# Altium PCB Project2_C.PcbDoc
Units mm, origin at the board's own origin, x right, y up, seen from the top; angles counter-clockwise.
Board outline 100 x 50 mm, 2 copper layers (Top Layer, Bottom Layer); 57 components, 59 nets, 255 pads, 69 vias.
Unrouted connection lines stored in the file: 2.
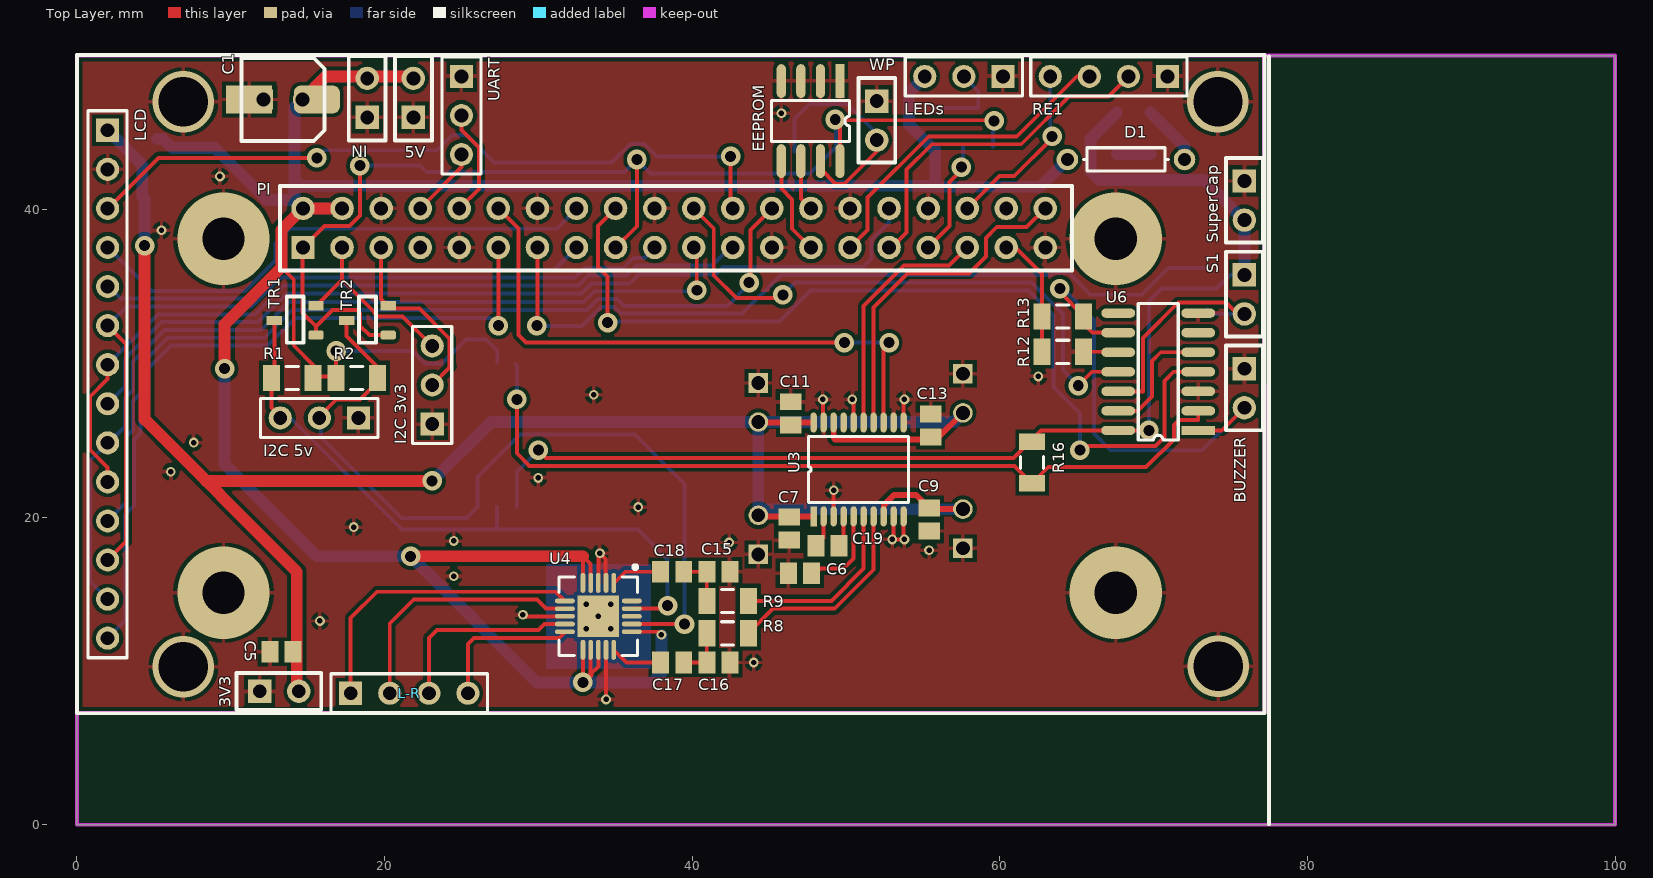
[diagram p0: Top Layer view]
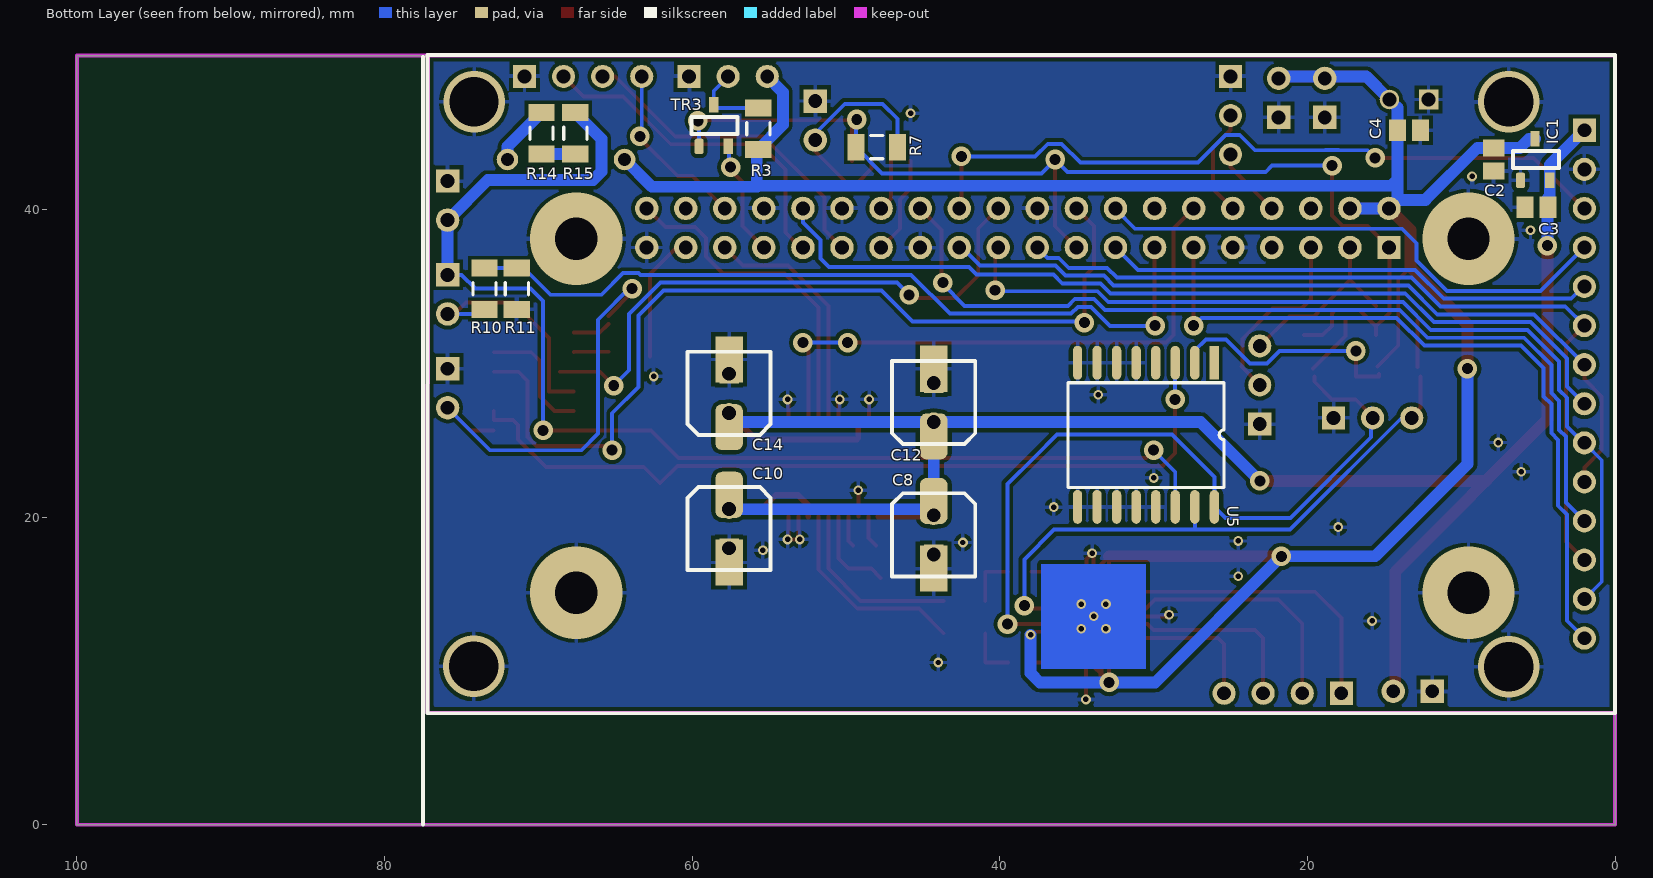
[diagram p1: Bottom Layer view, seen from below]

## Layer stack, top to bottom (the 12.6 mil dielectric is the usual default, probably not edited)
Top Solder: solder mask 0.0102, Solder Resist, Dk 3.5
Top Layer: signal copper 0.0356
Dielectric 1: dielectric 0.32, FR-4, Dk 4.8
Bottom Layer: signal copper 0.0356
Bottom Solder: solder mask 0.0102, Solder Resist, Dk 3.5

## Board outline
0,0 100,0 100,50 0,50

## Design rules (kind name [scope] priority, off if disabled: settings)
Clearance [All] p1: gap=0.254
PolygonConnect [All] p1: connectstyle=Relief reliefconductorwidth=0.254 reliefentries=4 polygonreliefangle="90 Angle" airgapwidth=0.254
RoutingVias [All] p1: holewidth=0.711 width=1.27 viastyle="Through Hole" minholewidth=0.711 minwidth=1.27 maxholewidth=0.711 maxwidth=1.27
SolderMaskExpansion [All] p1: expansion=0.102
Width [All] p1: maxlimit=1.524 minlimit=0.254 preferedwidth=0.254
30 further rules are at their usual default settings.

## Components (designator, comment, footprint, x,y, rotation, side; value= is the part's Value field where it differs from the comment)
3V3 "" HDR1X2 11.887,8.677 r0 top
5V "" HDR1X2 21.873,45.983 r90 top
BUZZER "" HDR1X2 75.9,29.65 r270 top
C1 "" "SMD CAP 6X5" 13.4,47.15 r180 top
C2 "" C0805 7.9,43.248 r90 bottom
C3 "" C0805 5.1,40.15 r180 bottom
C4 "" C0805 13.4,45.15 r0 bottom
C5 "" C0805 13.3,11.25 r180 top
C6 "" C0805 47,16.35 r0 top
C7 "" C0805 46.3,19.25 r270 top
C8 "" "SMD CAP 6X5" 44.3,18.85 r270 bottom
C9 "" C0805 55.4,19.85 r270 top
C10 "" "SMD CAP 6X5" 57.6,19.25 r270 bottom
C11 "" C0805 46.4,26.75 r270 top
C12 "" "SMD CAP 6X5" 44.3,27.45 r90 bottom
C13 "" C0805 55.5,25.95 r90 top
C14 "" "SMD CAP 6X5" 57.6,28.05 r90 bottom
C15 "" C0805 41.7,16.45 r0 top
C16 "" C0805 41.7,10.55 r0 top
C17 "" C0805 38.7,10.55 r0 top
C18 "" C0805 38.7,16.45 r0 top
C19 "" C0805 48.8,18.15 r0 top
D1 "" AXIAL-0.3 68.2,43.25 r0 top
EEPROM "I²C SERIAL EEPROM" SOIC-8 47.7,45.75 r270 top
"I2C 3v3" "" HDR1X3 23.1,26.05 r90 top
"I2C 5v" "" HDR1X3 18.3,26.45 r180 top
IC1 "3v3" SOT-23A 5.2,43.248 r180 bottom
IN "" HDR1X2 18.873,45.983 r90 top
L-R "Header 4" HDR1X4 17.8,8.55 r0 top
LCD "TJCTM24024-SPI" HDR1X14 2,45.15 r270 top locked
LEDs "WS2812" HDR1X3 60.2,48.65 r180 top
PI "Raspberry Pi v2" HDR2X10 38.83,38.8 r90 top locked
R1 "" C1206 14,29.05 r0 top
R2 "" C1206 18.2,29.05 r180 top
R3 "" C1206 55.7,45.25 r90 bottom
R7 "" C1206 48,44.05 r0 bottom
R8 "" C1206 42.3,12.45 r180 top
R9 "" C1206 42.3,14.55 r180 top
R10 "" C1206 73.5,34.85 r270 bottom
R11 "" C1206 71.4,34.85 r90 bottom
R12 "" C1206 64.1,30.75 r180 top
R13 "" C1206 64.1,33.05 r180 top
R14 "" C1206 69.8,44.95 r270 bottom
R15 "" C1206 67.6,44.95 r90 bottom
R16 "" C1206 62.1,23.55 r90 top
RE1 "RotaryEncoder" HDR1X4 70.9,48.65 r180 top
S1 "Alarm reset" HDR1X2 75.9,35.75 r270 top
SuperCap "Supercap" HDR1X2 75.9,41.85 r270 top
TR1 "Level shifter" SOT-23A 14.192,32.785 r90 top
TR2 "Level shifter" SOT-23A 18.885,32.785 r90 top
TR3 "Level shifter" SOT-23A 58.6,45.45 r180 bottom
U3 "I²S DAC" TSSOP-20 47.9,20.05 r90 top
U4 "TPA2016D2" QFN20-TPA2016D2 33.9,13.55 r270 top
U5 "DS3231 RTC" "DS3231 SO-16" 30.5,25.35 r270 bottom
U6 "NOR gates" SOIC-14 70.3,29.45 r180 top
UART "" HDR1X3 25,48.65 r270 top
WP "Jumper" HDR1X2 52,47.05 r270 top

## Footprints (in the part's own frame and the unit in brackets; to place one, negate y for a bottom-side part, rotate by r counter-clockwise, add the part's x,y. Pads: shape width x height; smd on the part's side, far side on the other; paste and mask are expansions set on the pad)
AXIAL-0.3 [mm] "Axial Device, Thru-Hole; 2 Leads; 0.3 in Pin Spacing"
  round 1.4 hole 0.85: 1(-3.81,0) 2(3.81,0)
  silkscreen extent -2.77,-0.76 2.77,0.76
C0805 [mm] "Chip Capacitor, Body 2.0x1.3mm, IPC High Density"
  rect 1.1x1.4 smd: 1(-0.75,0) 2(0.75,0)
  body extent -1.1,-0.72 1.1,0.72, height 1.4
C1206 [mm] "Chip Capacitor, Body 3.2x1.6mm, IPC High Density"
  rect 1.1x1.7 smd: 1(-1.35,0) 2(1.35,0)
  silkscreen extent -0.4,-0.75 0.4,0.75, body extent -1.7,-0.9 1.7,0.9, height 1.3
"DS3231 SO-16" [mm]
  rect 2.2x0.6 smd: 1(-4.685,4.445)
  oval 2.2x0.6 smd: 2(-4.685,3.175) 3(-4.685,1.905) 4(-4.685,0.635) 5(-4.685,-0.635) 6(-4.685,-1.905) 7(-4.685,-3.175) 8(-4.685,-4.445) 9(4.685,-4.445) 10(4.685,-3.175) 11(4.685,-1.905) 12(4.685,-0.635) 13(4.685,0.635) 14(4.685,1.905) 15(4.685,3.175) 16(4.685,4.445)
  silkscreen extent -3.38,-5.08 3.41,5.08
HDR1X2 [mil] "2 Pin Header"
  rect 60x60 hole 35.43: 1(0,0)
  round 60 hole 35.43: 2(100,0)
  silkscreen extent -59,-47 157,47
HDR1X3 [mm] "Connector; Header; 3 Position"
  rect 1.5x1.5 hole 0.9: 1(0,0)
  round 1.5 hole 0.9: 2(2.54,0) 3(5.08,0)
  silkscreen extent -1.27,-1.27 6.35,1.27
HDR1X4 [mm] "Connector; Header; 4 Position"
  rect 1.5x1.5 hole 0.9: 1(0,0)
  round 1.5 hole 0.9: 2(2.54,0) 3(5.08,0) 4(7.62,0)
  silkscreen extent -1.27,-1.27 8.89,1.27
HDR1X14 [mm] "Connector; Header; 14 Position"
  rect 1.5x1.5 hole 0.9: 1(0,0)
  round 1.5 hole 0.9: 2(2.54,0) 3(5.08,0) 4(7.62,0) 5(10.16,0) 6(12.7,0) 7(15.24,0) 8(17.78,0) 9(20.32,0) 10(22.86,0) 11(25.4,0) 12(27.94,0) 13(30.48,0) 14(33.02,0)
  silkscreen extent -1.27,-1.27 34.29,1.27
HDR2X10 [mil] "20 pin Header"
  rect 60x60 hole 35.43: 1(-50,950)
  round 60 hole 35.43: 2(50,950) 3(-50,850) 4(50,850) 5(-50,750) 6(50,750) 7(-50,650) 8(50,650) 9(-50,550) 10(50,550) 11(-50,450) 12(50,450) 13(-50,350) 14(50,350) 15(-50,250) 16(50,250) 17(-50,150) 18(50,150) 19(-50,50) 20(50,50) 21(-50,-50) 22(50,-50) 23(-50,-150) 24(50,-150) 25(-50,-250) 26(50,-250) 27(-50,-350) 28(50,-350) 29(-50,-450) 30(50,-450) 31(-50,-550) 32(50,-550) 33(-50,-650) 34(50,-650) 35(-50,-750) 36(50,-750) 37(-50,-850) 38(50,-850) 39(-50,-950) 40(50,-950)
  silkscreen extent -109,-1019 107,1009
QFN20-TPA2016D2 [mm] "QFN, 20-Leads, Body 4,77x4,77mm, Pitch 0,50mm, Thermal Pad 2,70x2,70mm, IPC Low Density"
  rect 2.7x2.7 smd: 0(0,0)
  oct 1.3x0.3 smd: 1(-2.175,1)
  oval 1.3x0.3 smd: 2(-2.175,0.5) 3(-2.175,0) 4(-2.175,-0.5) 5(-2.175,-1) 11(2.175,-1) 12(2.175,-0.5) 13(2.175,0) 14(2.175,0.5) 15(2.175,1)
  oval 0.3x1.3 smd: 6(-1,-2.175) 7(-0.5,-2.175) 8(0,-2.175) 9(0.5,-2.175) 10(1,-2.175) 16(1,2.175) 17(0.5,2.175) 18(0,2.175) 19(-0.5,2.175) 20(-1,2.175)
  silkscreen extent -3.32,-2.55 2.55,2.55, body extent -2.4,-2.4 2.4,2.4, height 0.8
"SMD CAP 6X5" [mm]
  rrect50% 3x1.8 smd: 1(-2.2,0)
  round 1.27 hole 0.9: 1(-1.27,0)
  rect 1.27x1.27 hole 0.9: 2(1.27,0)
  rect 3x1.8 smd: 2(2.2,0)
  silkscreen extent -2.7,-2.7 2.7,2.7
SOIC-8 [mm]
  rect 2.2x0.6 smd: 1(-2.6,1.905)
  oval 2.2x0.6 smd: 2(-2.6,0.635) 3(-2.6,-0.635) 4(-2.6,-1.905) 5(2.6,-1.905) 6(2.6,-0.635) 7(2.6,0.635) 8(2.6,1.905)
  silkscreen extent -1.33,-2.54 1.34,2.54
SOIC-14 [mm]
  rect 2.2x0.6 smd: 1(-2.6,3.81)
  oval 2.2x0.6 smd: 2(-2.6,2.54) 3(-2.6,1.27) 4(-2.6,0) 5(-2.6,-1.27) 6(-2.6,-2.54) 7(-2.6,-3.81) 8(2.6,-3.81) 9(2.6,-2.54) 10(2.6,-1.27) 11(2.6,0) 12(2.6,1.27) 13(2.6,2.54) 14(2.6,3.81)
  silkscreen extent -1.3,-4.44 1.3,4.44
SOT-23A [mm]
  rrect50% 0.6x1 smd: 1(-0.95,-1.35)
  rect 0.6x1 smd: 2(0.95,-1.35) 3(0,1.35)
  silkscreen extent -1.45,-0.55 1.55,0.55
TSSOP-20 [mm]
  rect 1.3x0.4 smd: 1(0,0)
  oval 1.3x0.4 smd: 2(0,-0.65) 3(0,-1.3) 4(0,-1.95) 5(0,-2.6) 6(0,-3.25) 7(0,-3.9) 8(0,-4.55) 9(0,-5.2) 10(0,-5.85) 11(6.1,-5.85) 12(6.1,-5.2) 13(6.1,-4.55) 14(6.1,-3.9) 15(6.1,-3.25) 16(6.1,-2.6) 17(6.1,-1.95) 18(6.1,-1.3) 19(6.1,-0.65) 20(6.1,0)
  silkscreen extent 0.9,-6.18 5.2,0.33

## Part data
3V3 5V IN: library part "Header 2", "Header, 2-Pin"
BUZZER: library part Bell, "Electrical Bell"
C1 SuperCap: library part "Cap Pol1", "Polarized Capacitor (Radial)"
C2 C3 C4 C5 C6 C7 C9 C11 C13 C15 C16 C17 C18 C19: library part Cap, "Capacitor"
C8 C10 C12 C14: library part "Cap Pol2", "Polarized Capacitor (Axial)"
D1: library part Diode, "Default Diode"
"I2C 3v3" "I2C 5v" LEDs UART: library part "Header 3", "Header, 3-Pin"
IC1: library part MCP1703, "Power regulator"
L-R: "Header, 4-Pin"
LCD: "LCD module"
PI: library part RaspberryPiV2, "Raspberry Pi v2 Header"
R1 R2 R3 R7 R8 R9 R10 R11 R12 R13 R14 R15 R16: library part Res2, "Resistor"
RE1: library part "Header 4", "Header, 4-Pin"
S1: library part SW-PB, "Switch"
TR1 TR2 TR3: library part AN10441, "Level Shifter"
U3: library part PCM5102A
U4: "I²C Audio Amplifier"
U5: library part DS3231, "RTC"
U6: library part 744002, "Dual 4-input NOR gate"

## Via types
v1: diameter 1.27, hole 0.711, Top Layer to Bottom Layer, tented both sides, 30 vias
v2: diameter 0.635, hole 0.356, Top Layer to Bottom Layer, tented both sides, 26 vias
v3: diameter 0.635, hole 0.356, Top Layer to Bottom Layer, 5 vias
v4: diameter 4, hole 3.2, Top Layer to Bottom Layer, 4 vias
v5: diameter 6, hole 2.75, Top Layer to Bottom Layer, 4 vias

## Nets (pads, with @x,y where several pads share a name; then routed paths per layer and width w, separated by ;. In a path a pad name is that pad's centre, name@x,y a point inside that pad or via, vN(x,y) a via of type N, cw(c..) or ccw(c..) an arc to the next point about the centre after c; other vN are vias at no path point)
3V3: 3V3.2 C3.2 C5.1 C7.1 C8.1 C9.1 C10.1 C11.2 C12.1 C13.1 C14.1 IC1.2 LCD.1 U3.1 U3.8 U3.17 U3.18 U3.20 | length 136.1
  Top Layer w0.381: C8.1@44.3,20.12 44.37,20.05 U3.1 ; C12.1@44.3,26.18 44.33,26.15 U3.20 ; U3.18 49.206,26.15 49.206,25.142 49.292,25.055 55.875,25.055 C14.1@57.6,26.78 ; U3.8 52.456,20.055 52.456,20.767 53.139,21.45 54.55,21.45 C9.1 55.48,20.52 C10.1@57.6,20.52
  Top Layer w0.762: v1(4.4,37.65) 4.4,26.35 14.3,16.45 3V3.2@14.3,8.55 ; 8.4,22.35 v1(23.1,22.35)
  Bottom Layer w0.762: LCD.1@1.965,45.15 LCD.1 4.25,42.9 C3.2@4.25,40.85 ; C3.2@4.35,40.75 4.4,40.7 v1(4.4,37.65) ; v1(23.1,22.35) 26.93,26.18 C12.1@44.3,26.18 ; C10.1@57.6,20.52 44.7,20.52 44.3,20.12 44.3,21.05 44.3,25.25 C12.1@44.3,26.18 ; C14.1@57.6,26.78 57,26.18 C12.1@44.3,26.18
3V3PI: EEPROM.8 PI.1 PI.17 R7.2 TR1.1 TR2.1 TR3.1 | length 76.2
  Top Layer w0.254: v1(18.4,42.85) 18.4,39.614 17.713,38.927 16.097,38.927 PI.1 14.661,37.491 14.661,33.277 14.884,33.054 14.896,33.054 15.542,32.408 ; TR2.1 19.015,31.835 18.416,32.434 18.416,33.243 18.193,33.466 16.616,33.466 15.55,32.4 15.542,32.408 ; PI.17 36.4,38.91 v1(36.4,43.25) ; EEPROM.8 49.605,45.345 49.3,45.65 v1(49.3,45.85) 49.35,45.8 v1@59.4,45.8 ; v1@59.434,45.766 v1(59.623,45.766) ; 15.542,32.408 TR1.1 15.542,32.408
  Bottom Layer w0.254: v1(18.4,42.85) 22.3,42.85 22.711,42.439 35.589,42.439 v1(36.4,43.25) 37.3,42.35 47.65,42.35 R7.2 49.35,45.8 v1(49.3,45.85) ; TR3.1 59.55,45.693 v1(59.623,45.766)
5V: 5V.2 C1.1 C2.2 C4.2 D1.1 IC1.3 IN.2 LEDs.3 PI.2 PI.4 R1.2 R2.2 R3.1 U4.4 U4.5 U4.11 U4.12 U4.13 U4.16 U5.2 | length 200
  Top Layer w0.254: 13.303,36.247 14.1,35.45 14.1,31.15 R1.2@15.45,29.8 ; R1.2@15.35,29.3 15.35,29.15 16.85,29.15 v1(16.85,30.8) ; v1@32.9,9.65 U4.11 ; U4.5 32.9,17.45 33.4,16.95 U4.4 ; 33.4,9.75 33.4,9.8 ; U4.12 33.4,9.8 ; U4.13 33.9,10.3 33.4,9.8 ; U4.16 37.8,12.55 v2(38,12.35)
  Top Layer w0.381: v1(32.9,9.25) 33.4,9.75
  Top Layer w0.762: v1(9.6,29.65) 9.6,32.544 13.303,36.247 13.303,38.673 PI.2 PI.4 ; C1.1@14.67,47.15 16.17,48.65 5V.2@22,48.65 ; v1(21.7,17.45) 32.9,17.45
  Bottom Layer w0.254: v1(16.85,30.8) 21.831,30.8 22.632,29.999 23.749,29.999 25.3,31.55 26.6,31.55 27.325,30.825 U5.2
  Bottom Layer w0.762: IC1.3 5.595,44.598 6.195,43.998 C2.2 8.952,43.998 12.33,40.62 14.15,40.62 ; v1(9.6,29.65) 9.6,23.45 15.6,17.45 v1(21.7,17.45) 29.9,9.25 v1(32.9,9.25) 37.4,9.25 38,9.85 v2(38,12.35) ; PI.4 PI.2 14.15,40.62 ; 5V.2@22,48.65 16.17,48.65 14.67,47.15 14.15,46.63 C4.2 14.15,41.95 ; LEDs.3 54.1,47.63 54.1,45.5 R3.1 ; 55.8,41.65 R3.1@55.8,43.9 ; D1.1 62.62,41.48 55.77,41.48 55.7,41.55 14.55,41.55 14.15,41.95 ; 14.15,40.62 14.15,41.95
5VBCK: R15.2 R16.2 S1.1 SuperCap.2 U5.14 U6.14 | length 79.6
  Top Layer w0.254: v1(30,24.35) 30.5,23.85 60.9,23.85 62.69,25.64 U6.14 v1(69.69,25.64)
  Bottom Layer w0.254: U5.14 28.595,22.945 v1(30,24.35) ; v1(69.69,25.64) 69.69,34.04 70.5,34.85 74.089,34.85 74.989,35.75 S1.1
  Bottom Layer w0.762: R15.2 65.9,44.6 65.9,42.45 66.435,41.915 73.295,41.915 SuperCap.2 S1.1
BUZZ: PI.37 R12.2 R13.2 | length 8.4
  Top Layer w0.254: PI.37 61.02,37.53 62.75,35.8 R12.2@62.75,30.45
"CE 0": LCD.3 PI.24 | length 47.7
  Top Layer w0.254: LCD.3 2.02,40.07 5.3,43.35 v1(15.6,43.35) ; v1@42.5,43.67 42.5,40.21 PI.24
  Bottom Layer w0.254: v1(15.6,43.35) 16.1,43.85 17.963,43.85 17.979,43.866 18.821,43.866 18.837,43.85 23.4,43.85 24.4,44.85 25.319,44.85 27.119,43.05 34.763,43.05 35.979,44.266 36.884,44.266 37.7,43.45 v1(42.5,43.45)
"CE 1": LCD.11 PI.26 | length 58.7
  Top Layer w0.254: v1(43.7,35.25) 43.783,35.333 43.783,38.673 PI.26
  Bottom Layer w0.254: LCD.11 3.2,20.95 3.2,25.232 3.639,25.671 3.639,27.552 4.147,28.06 4.147,29.897 5.911,31.661 12.193,31.661 13.998,33.466 33.161,33.466 33.869,34.174 35.131,34.174 35.571,33.734 42.284,33.734 43.7,35.15 v1(43.7,35.25)
CLK: PI.12 U3.13 | length 38.6
  Top Layer w0.254: PI.12 28.7,38.77 28.7,31.85 29.2,31.35 v1(49.9,31.35) ; U3.13 52.45,31.3 52.5,31.35 v1(52.8,31.35)
  Bottom Layer w0.254: v1(49.9,31.35) v1(52.8,31.35)
DC_LCD: LCD.5 PI.15 | length 32.2
  Bottom Layer w0.254: LCD.5 2.06,34.99 2.849,34.201 11.141,34.201 13.014,36.074 31.024,36.074 PI.15
DIN: PI.38
DOUT: PI.40 U3.14 | length 22
  Top Layer w0.254: U3.14 51.784,26.166 51.784,33.634 53.992,35.842 56.91,35.842 56.918,35.85 58,35.85 59.1,36.95 59.1,38.15 59.8,38.85 61.74,38.85 PI.40
FS: PI.35 U3.15 | length 15.9
  Top Layer w0.254: U3.15 51.15,33.718 53.782,36.35 56.7,36.35 PI.35
GND: 3V3.1 5V.1 "I2C 3v3.1" "I2C 5v.1" BUZZER.1 C1.2 C2.1 C3.1 C4.1 C5.2 C6.1 C7.2 C8.2 C9.2 C10.2 C11.1 C12.2 C13.2 C14.2 C15.2 C16.2 EEPROM.1 EEPROM.2 EEPROM.3 EEPROM.4 IC1.1 IN.1 LCD.2 LEDs.1 PI.6 PI.9 PI.14 PI.20 PI.25 PI.30 PI.34 PI.39 R11.1 R12.1 RE1.1 SuperCap.1 U3.3 U3.9 U3.10 U3.11 U3.12 U3.16 U3.19 U4.2 U4.3 U4.8 U4.14 U5.5 U5.6 U5.7 U5.8 U5.9 U5.10 U5.11 U5.12 U5.13 U6.3 U6.7 U6.10 UART.1 WP.1 | length 22.1
  Top Layer w0.254: v2(29,13.65) 29.1,13.55 U4.8 ; U4.3 33.9,17.55 v2(34,17.65) 34.369,17.281 U4.2@34.369,15.725 ; v2(34.4,8.15) U4.14 ; U3.19@48.5,26.2 v2(48.5,27.65) ; U3.3 v2(49.2,21.75) ; v2(50.4,27.65) 50.5,27.55 U3.16 ; v2(53,18.55) v2(53.8,18.55) ; v2@53.1,18.65 U3.9 ; v2@53.75,18.6 U3.10 ; U3.11 v2@53.75,27.6 ; R12.1 67.67,30.75 U6.10
  other v2: 44,10.55 15.8,13.25 24.5,16.15 55.4,17.85 42.4,18.35 24.5,18.45 18,19.35 36.5,20.65 30,22.55 6.1,22.95 7.6,24.85 53.8,27.65 33.6,27.95 62.5,29.15 5.5,38.65 9.3,42.15 45.8,46.25
  other v4: 6.92,10.27 74.2,10.3 6.92,47 74.18,47
  other v5: 9.53,15.09 67.53,15.09 9.53,38.09 67.53,38.09
IRQ: LCD.14 PI.11 | length 48
  Top Layer w0.254: v1(27.4,32.45) PI.11
  Bottom Layer w0.254: LCD.14 3.131,13.261 3.131,20.163 3.708,20.74 3.708,25.021 4.147,25.46 4.147,27.342 4.655,27.85 4.655,29.687 6.121,31.153 12.403,31.153 14.2,32.95 26.9,32.95 v1(27.4,32.45)
MISO: LCD.9 LCD.13 PI.21 | length 58.7
  Top Layer w0.254: PI.21 40.3,37.33 v1(40.3,34.75)
  Bottom Layer w0.254: LCD.13 0.869,15.801 0.869,23.699 LCD.9 2.115,24.945 2.195,24.945 3.131,25.881 3.131,27.763 3.639,28.271 3.639,30.107 5.701,32.169 11.983,32.169 13.788,33.974 32.95,33.974 33.658,34.682 40.368,34.682 v1(40.3,34.75)
MOSI: LCD.6 LCD.12 PI.19 | length 53.9
  Top Layer w0.254: LCD.12 3.2,18.41 3.2,31.25 LCD.6
  Bottom Layer w0.254: LCD.6 3.243,33.693 11.351,33.693 13.224,35.566 32.387,35.566 33.027,36.206 35.519,36.206 36.171,36.858 36.888,36.858 PI.19
NetBUZZER_2: BUZZER.2 R13.1 U6.1 U6.9 | length 30.6
  Top Layer w0.254: v1(63.9,34.85) 63.9,34.634 R13.1@65.45,33.084 ; R13.1@65.45,32.55 66.01,31.99 U6.9 ; U6.1 74.43,25.64 BUZZER.2
  Bottom Layer w0.254: v1(63.9,34.85) 63.9,35.05 66.116,32.834 66.116,25.434 67.2,24.35 73.14,24.35 BUZZER.2
NetC6_2: C6.2 U3.5 | length 6
  Top Layer w0.254: C6.2@47.75,16.05 48.35,16.65 49.839,16.65 50.5,17.311 U3.5
NetC15_1: C15.1 C18.2 R9.2 | length 3.4
  Top Layer w0.254: C18.2 C15.1 R9.2
NetC16_1: C16.1 C17.2 R8.2 | length 3.4
  Top Layer w0.254: C17.2 C16.1 R8.2
NetC17_1: C17.1 U4.15 | length 3.4
  Top Layer w0.254: U4.15 35.725,10.55 C17.1
NetC18_1: C18.1 U4.1 | length 3.3
  Top Layer w0.254: U4.1@34.931,15.725 35.656,16.45 C18.1
NetC19_1: C19.1 U3.2 | length 2.1
  Top Layer w0.254: C19.1 48.55,18.65 U3.2
NetC19_2: C19.2 U3.4 | length 2
  Top Layer w0.254: C19.2 49.85,18.45 U3.4
NetD1_2: D1.2 R14.1 | length 4
  Bottom Layer w0.762: R14.1 72.01,44.09 D1.2
NetEEPROM_5: EEPROM.5 PI.27 | length 6.4
  Top Layer w0.254: EEPROM.5 45.795,41.355 46.5,40.65 46.5,38.75 PI.27
NetEEPROM_6: EEPROM.6 PI.28 | length 3.4
  Top Layer w0.254: EEPROM.6 47.065,40.725 PI.28
NetEEPROM_7: EEPROM.7 R7.1 WP.2 | length 15.5
  Top Layer w0.254: EEPROM.7 48.335,42.657 49.323,41.669 49.887,41.669 52,43.782 WP.2 WP.2@51.879,44.631
  Bottom Layer w0.254: R7.1@46.65,43.75 46.65,45.9 47.616,46.866 50.084,46.866 52,44.95 WP.2
"NetI2C 5v_2": "I2C 5v.2" R2.1 TR2.3 U4.17 U5.16 | length 54
  Top Layer w0.254: 15.8,26.55 15.76,26.55 16.86,27.65 18.4,27.65 19.55,28.8 R2.1@19.55,29.15 ; TR2.3 17.535,31.765 R2.1@19.65,29.65 ; U4.17 v1(39.5,13.05)
  Bottom Layer w0.254: 15.86,27.05 15.86,25.19 21.1,19.95 25.34,19.95 U5.16 26.055,22.605 28.816,25.366 36.284,25.366 37.764,23.886 39.5,22.15 v1(39.5,13.05)
"NetI2C 5v_3": "I2C 5v.3" R1.1 TR1.3 U4.19 U5.15 | length 42.1
  Top Layer w0.254: R1.1@12.65,29.15 12.65,27.12 13.22,26.55 ; R1.1@12.842,29.742 TR1.3 ; U4.19 38.4,14.05 v1(38.4,14.25)
  Bottom Layer w0.254: 13.32,27.05 13.32,27.012 21.148,19.184 27.3,19.184 ; U5.15 27.3,20.665 27.3,19.184 ; v1(38.4,14.25) 38.4,17.25 36.466,19.184 27.3,19.184
NetL-R_1: L-R.1 U4.6 | length 19.8
  Top Layer w0.254: L-R.1 17.8,13.45 19.5,15.15 31.125,15.15 U4.6
NetL-R_2: L-R.2 U4.7 | length 16.8
  Top Layer w0.254: L-R.2 20.34,13.082 21.9,14.642 29.908,14.642 30.5,14.05 U4.7
NetL-R_3: L-R.3 U4.9 | length 12.8
  Top Layer w0.254: L-R.3 22.88,12.13 23.408,12.658 30.008,12.658 30.4,13.05 U4.9
NetL-R_4: L-R.4 U4.10 | length 9.8
  Top Layer w0.254: L-R.4 25.42,11.762 25.808,12.15 31.356,12.15 U4.10@31.725,12.519
NetLEDs_2: LEDs.2 R3.2 TR3.3 | length 5.3
  Bottom Layer w0.254: R3.2 58.6,46.6 58.6,47.71 LEDs.2
NetR8_1: R8.1 U3.7 | length 13.3
  Top Layer w0.254: R8.1 45.25,14.05 49.268,14.05 51.8,16.582 U3.7
NetR9_1: R9.1 U3.6 | length 11.8
  Top Layer w0.254: R9.1 45.032,14.55 45.04,14.558 49.058,14.558 51.15,16.65 U3.6
NetR10_2: R10.2 S1.2 U6.12 | length 15.4
  Top Layer w0.254: U6.12 69.3,28.18 69.3,31.65 71.6,33.95 74.7,33.95 75.44,33.21 S1.2
  Bottom Layer w0.254: R10.2 73.79,33.21 S1.2
NetR14_2: R14.2 R15.1 | length 2.2
  Bottom Layer w0.762: R15.1 R14.2
NetR16_1: R16.1 U5.3 U6.2 | length 53.8
  Top Layer w0.254: v1(28.6,27.65) 28.6,24.15 29.4,23.35 29.4,23.334 60.966,23.334 R16.1 63.15,23.25 69.516,23.25 71.316,25.05 71.316,25.995 71.642,26.321 72.9,26.321 U6.2
  Bottom Layer w0.254: U5.3@28.5,29.94 28.6,29.84 v1(28.6,27.65)
NetRE2_1: 
NetRE2_2: 
NetRE2_3: 
NetRE2_4: 
NetU6_5: U6.5 U6.13 | length 8.1
  Top Layer w0.254: U6.13 68.96,26.91 69.9,27.85 69.9,30.16 70.46,30.72 U6.5
"PWM 0": LCD.8 PI.32 | length 58.4
  Bottom Layer w0.254: LCD.8 2.004,27.374 2.024,27.374 3.131,28.481 3.131,30.318 5.49,32.677 11.772,32.677 13.645,34.55 32.808,34.55 33.448,35.19 35.94,35.19 36.516,35.766 41.516,35.766 42.016,36.266 51.116,36.266 51.657,36.807 51.657,38.003 52.8,39.146 PI.32
"PWM 1": PI.33 TR3.2 | length 7.3
  Top Layer w0.254: PI.33 56.737,38.927 56.737,41.787 v1@57.5,42.55
  Bottom Layer w0.254: v1(57.5,42.75) 57.6,42.85 TR3.2@57.6,44.05
RE_A: PI.36 RE1.4 | length 11.8
  Top Layer w0.254: PI.36 59.979,42.169 60.937,42.169 v1@63.318,44.55
  Bottom Layer w0.254: PI.36 PI.36@58.42,40.07 ; RE1.4 63.28,44.87 v1(63.4,44.75)
RE_B: PI.29 RE1.3 | length 21.4
  Top Layer w0.254: PI.29 50.28,37.53 51.403,38.653 51.403,40.771 55.382,44.75 61.1,44.75 65,48.65 RE1.3
RE_S: PI.31 RE1.2 | length 22.6
  Top Layer w0.254: PI.31 52.98,37.53 53.943,38.493 53.943,42.593 55.592,44.242 61.392,44.242 64.5,47.35 67.06,47.35 RE1.2
RESET: PI.22 U6.11 | length 38.4
  Top Layer w0.254: PI.22 41.4,38.77 41.4,35.713 42.879,34.234 45.684,34.234 v1(45.9,34.45) ; v1(65.1,28.55) 66,29.45 U6.11 U6.11@68.6,29.45
  Bottom Layer w0.254: v1(45.9,34.45) 46.692,35.242 62.071,35.242 64.1,33.213 64.1,29.55 v1(65.1,28.55)
RESET_LCD: LCD.4 PI.16 | length 34.6
  Bottom Layer w0.254: LCD.4 2.02,37.55 2.02,37.53 4.841,34.709 10.93,34.709 12.911,36.69 12.911,37.804 13.857,38.75 31.2,38.75 32.48,40.03 PI.16
RX: PI.10 UART.2 | length 7
  Top Layer w0.254: PI.10 26.131,41.341 26.131,44.038 25,45.169 UART.2
SCK: "I2C 3v3.2" PI.5 TR2.2 | length 12.4
  Top Layer w0.254: PI.5 19.78,34.19 TR2.2 20.408,33.562 22.267,33.562 24.231,31.598 24.231,29.859 24.3,29.79 23.1,28.59
SCLK: LCD.7 LCD.10 PI.23 | length 52.4
  Top Layer w0.254: LCD.10 2,23.231 0.869,24.362 0.869,27.838 2,28.969 LCD.7
  Bottom Layer w0.254: LCD.7 5.275,33.185 11.562,33.185 13.435,35.058 32.597,35.058 33.237,35.698 35.73,35.698 36.382,36.35 41.286,36.35 42.466,37.53 PI.23
SDA: "I2C 3v3.3" PI.3 TR1.2 | length 12.2
  Top Layer w0.254: TR1.2 17.24,35.433 ; PI.3 17.24,35.433 ; 23.1,31.13 21.176,33.054 19.577,33.054 19.354,33.277 19.354,33.319 17.24,35.433
SET: PI.18 U6.4 | length 60.5
  Top Layer w0.254: v1(34.5,32.65) 34.5,35.634 34.508,35.642 33.877,36.273 33.877,38.927 PI.18 ; v1(65.2,24.35) 65.2,24.398 65.426,24.624 70.111,24.624 70.706,25.219 70.706,28.856 71.3,29.45 U6.4
  Bottom Layer w0.254: v1(34.5,32.65) 34.5,32.35 34.868,32.718 45.668,32.718 47.684,34.734 61.861,34.734 63.5,33.095 63.5,28.45 65.2,26.75 v1(65.2,24.35)
SW: PI.13 R10.1 R11.2 | length 51.8
  Top Layer w0.254: v1(29.9,32.45) 29.94,32.49 PI.13
  Bottom Layer w0.254: v1(29.9,32.45) 29.924,32.426 32.839,32.426 34.079,33.666 34.921,33.666 35.361,33.226 43.239,33.226 45.763,35.75 63.363,35.75 63.479,35.866 64.484,35.866 65.892,34.458 69.208,34.458 70.95,36.2 R11.2 R10.1
TX: PI.8 UART.3 | length 4.6
  Top Layer w0.254: PI.8 25,42.75 UART.3
pads on no net: PI.7 U4.0 U4.18 U4.20 U5.1 U5.4 U6.6 U6.8
copper on no net:
  other v3: 33.1,12.75 34.7,12.75 33.9,13.55 33.1,14.35 34.7,14.35

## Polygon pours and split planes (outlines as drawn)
GND on Bottom Layer "GND_L02_P000" (solid, remove dead copper, pour order 0): 0,50 77.175,50 77.175,7.3 77.175,7.275 0,7.275
GND on Top Layer "GND_L01_P002" (solid, remove dead copper, pour order 2): 0,50 0,7.3 77.175,7.3 77.175,50

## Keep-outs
Keep-Out Layer:
  lines w0.254: 0,7.3 77.18,7.28 ; 77.18,50 77.2,7.3 ; 0,0 0,50 100,50 100,0 0,0

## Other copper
Bottom Layer:
  region: 30.5,10.15 37.3,10.15 37.3,16.95 30.5,16.95

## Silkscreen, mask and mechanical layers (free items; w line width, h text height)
Top Overlay:
  lines w0.254: 77.5,0.05 77.5,49.95 ; 0,7.25 0,50.05 77.2,50.05 77.2,7.25 0,7.25
Bottom Overlay:
  lines w0.254: 77.5,0 77.5,49.9 ; 0,7.25 0,50.05 77.2,50.05 77.2,7.25 0,7.25
Mechanical 1:
  lines w0.254: 37.43,11.59 37.43,-10.41 57.43,-10.41 57.43,11.59 ; 77.18,7.28 0,7.3 0,50 ; 77.2,7.3 77.18,50 0,50 ; 0,50 100,50 100,0 0,0 0,50 ; 6.03,14.59 ccw(c9.03,14.59) 9.03,11.59 68.03,11.59 ccw(c68.03,14.59) 71.03,14.59 71.03,38.59 ccw(c68.03,38.59) 68.03,41.59 9.03,41.59 ccw(c9.03,38.59) 6.03,38.59 6.03,14.59
  text "WiFi" at 44.13,-0.65 h2.29
Mechanical 13:
  the board outline again, w0.254
Mechanical 15:
  the board outline again, w0.254

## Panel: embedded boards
"..\..\..\..\Altium\Projects\WS2812\Stick2.PcbDoc" at 0,0, 1 rows x 1 columns, spacing 63.5 x 38.1, rotation 0
"..\..\..\..\Altium\Projects\WS2812\Rect.PcbDoc" at 77.8,0, 1 rows x 1 columns, spacing 63.5 x 38.1, rotation 0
